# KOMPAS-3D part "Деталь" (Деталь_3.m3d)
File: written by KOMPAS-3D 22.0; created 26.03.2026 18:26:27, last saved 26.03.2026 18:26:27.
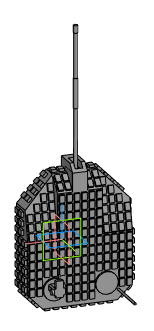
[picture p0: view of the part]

Document properties: Автор: Пользователь Windows; Полное имя файла: F:\Танк\Деталь_3.m3d

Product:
- Part/product: Деталь

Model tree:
1. Операция без истории:1
2. Операция без истории:2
